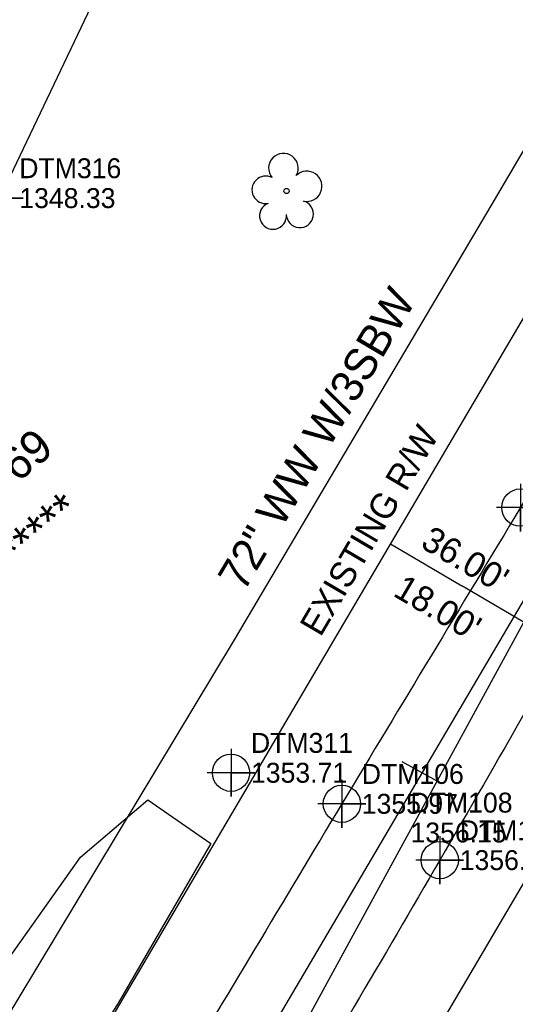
# Model space of a CAD drawing. Extents: x 1435573 to 1437263, y 981340 to 982884.
# Drawn here: x 1436076 to 1436138.2, y 982245.5 to 982369.2 of the extents above; entities that cross this region are included whole.
import ezdxf

# ---------------------------------------------------------------- set-up
doc = ezdxf.new("R2010")
doc.units = 0
for name, color, linetype in [('CTL Sheet Text', 7, 'Continuous'), ('Default Symbol CELL', 7, 'Continuous'), ('Default Symbol Cogo Elevation', 7, 'Continuous'), ('Default Symbol Cogo Number', 7, 'Continuous'), ('Exist DTM Crownline Cogo Elevation', 7, 'Continuous'), ('Exist DTM Crownline Cogo Number', 7, 'Continuous'), ('Exist Horizontal Alignment', 7, 'Continuous'), ('Exist Horizontal Baseline Alignment', 7, 'Continuous'), ('Exist Horizontal Baseline Alignment Tick small', 7, 'Continuous'), ('Exist Hydro Jurisdictional Stream or Body of Water', 7, 'Continuous'), ('Exist Hydro Stream or Body of Water Cogo Elevation', 7, 'Continuous'), ('Exist Hydro Stream or Body of Water Cogo Number', 7, 'Continuous'), ('Exist Hydro Stream or Body of Water Cogo Point CELL', 7, 'Continuous'), ('Exist Other Culture Fence Line', 7, 'Continuous'), ('Exist Other Culture Fence Line Text', 7, 'Continuous'), ('Exist Right of Way Line', 7, 'Continuous'), ('Exist Right of Way Line Text', 7, 'Continuous'), ('Exist Right of Way Width CELL', 7, 'Continuous'), ('Exist Roads EOP', 7, 'Continuous'), ('Exist Roads EOP Cogo Elevation', 7, 'Continuous'), ('Exist Roads EOP Cogo Number', 7, 'Continuous'), ('Exist Roads EOP Cogo Point CELL', 7, 'Continuous'), ('Exist Vegetation Tree CELL', 7, 'Continuous'), ('Exist Vegetation Woods Line', 7, 'Continuous')]:
    doc.layers.add(name, color=color, linetype=linetype)

msp = doc.modelspace()

# ---------------------------------------------------------------- linework, layer by layer
at = {"layer": 'Default Symbol CELL'}
msp.add_lwpolyline([(1436102.53, 982277.61), (1436102.53, 982271.61), (1436102.53, 982274.61), (1436105.53, 982274.61), (1436099.53, 982274.61)], dxfattribs=at)
msp.add_circle((1436102.53, 982274.61), 2.34, dxfattribs=at)
at = {"layer": 'Exist Horizontal Alignment'}
msp.add_line((1436018.3, 982090.66), (1436160.98, 982333.13), dxfattribs=at)
at = {"layer": 'Exist Horizontal Baseline Alignment'}
msp.add_line((1435840.71, 981747.05), (1436220.79, 982442.59), dxfattribs=at)
at = {"layer": 'Exist Horizontal Baseline Alignment Tick small'}
msp.add_line((1436128.43, 982273.57), (1436124.04, 982275.97), dxfattribs=at)
at = {"layer": 'Exist Hydro Jurisdictional Stream or Body of Water'}
msp.add_lwpolyline([(1435868.19, 982015.59), (1435900.37, 982051.1), (1435890.46, 982068.11), (1435899.75, 982073.74), (1435922.56, 982111.64), (1435976.46, 982187.79), (1435990.17, 982221.39), (1436012.44, 982254.73), (1436035.55, 982280.88), (1436050.71, 982320.86), (1436073.43, 982346.77), (1436085.85, 982372.72), (1436095.83, 982388.72), (1436115.7, 982405.3)], dxfattribs=at)
at = {"layer": 'Exist Hydro Stream or Body of Water Cogo Point CELL'}
msp.add_lwpolyline([(1436070.43, 982346.77), (1436076.43, 982346.77), (1436073.43, 982346.77), (1436073.43, 982343.77), (1436073.43, 982349.77)], dxfattribs=at)
at = {"layer": 'Exist Other Culture Fence Line'}
msp.add_lwpolyline([(1435979.98, 982088.94), (1436003.47, 982127.28), (1436023.88, 982160.05), (1436102.97, 982291.31), (1436135.2, 982345.79), (1436142.87, 982358.83), (1436158.39, 982359.45)], dxfattribs=at)
at = {"layer": 'Exist Right of Way Line'}
for p, q in [((1436002.79, 982099.79), (1436145.47, 982342.25)), ((1436033.82, 982081.53), (1436176.49, 982324))]:
    msp.add_line(p, q, dxfattribs=at)
at = {"layer": 'Exist Right of Way Width CELL'}
for p in [(1436122.57, 982303.34), (1436153.6, 982285.08)]:
    msp.add_line(p, (1436131.53, 982298.07), dxfattribs=at)
at = {"layer": 'Exist Roads EOP'}
for points in [[(1436168.25, 982354.25), (1436159.59, 982341.51), (1436138.87, 982307.91), (1436116.45, 982270.71), (1436094.59, 982234.3), (1436072.39, 982197.46), (1436049.68, 982158.52), (1436026.6, 982119.74), (1436003.23, 982078.86), (1435983.99, 982044.69), (1435963.78, 982007.01), (1435943.65, 981966.84), (1435922.15, 981922.09), (1435903.52, 981881.23), (1435884.45, 981840.59), (1435866.4, 981798.52)], [(1436177.12, 982349.86), (1436168.84, 982336.18), (1436150.23, 982301.68), (1436128.75, 982263.64), (1436107.21, 982226.88), (1436085.56, 982190.23), (1436062.44, 982151.3), (1436039.53, 982112.34), (1436015.81, 982071.47), (1435996.75, 982037.94), (1435976.48, 982000.31), (1435956.5, 981960.4), (1435935.19, 981915.99), (1435916.41, 981875.42), (1435898.23, 981835.84), (1435879.29, 981793.08)]]:
    msp.add_spline(points, degree=3, dxfattribs=at)
at = {"layer": 'Exist Roads EOP Cogo Point CELL'}
for points in [[(1436138.87, 982310.91), (1436138.87, 982304.91), (1436138.87, 982307.91), (1436141.87, 982307.91), (1436135.87, 982307.91)], [(1436116.45, 982273.71), (1436116.45, 982267.71), (1436116.45, 982270.71), (1436119.45, 982270.71), (1436113.45, 982270.71)], [(1436128.75, 982266.64), (1436128.75, 982260.64), (1436128.75, 982263.64), (1436131.75, 982263.64), (1436125.75, 982263.64)]]:
    msp.add_lwpolyline(points, dxfattribs=at)
for centre in [(1436138.87, 982307.91), (1436116.45, 982270.71), (1436128.75, 982263.64)]:
    msp.add_circle(centre, 2.34, dxfattribs=at)
at = {"layer": 'Exist Vegetation Tree CELL'}
msp.add_line((1436109.5, 982347.66), (1436109.5, 982347.66), dxfattribs=at)
msp.add_circle((1436109.5, 982347.66), 0.326, dxfattribs=at)
for centre, radius, start, end in [((1436109.11, 982350.53), 1.86, 330.1651, 219.7134), ((1436112.05, 982348.25), 1.9, 257.1011, 134.1999), ((1436106.89, 982347.81), 1.73, 62.6636, 279.3457), ((1436111.17, 982344.76), 1.7, 181.2822, 74.56), ((1436107.8, 982344.54), 1.69, 111.5671, 6.231)]:
    msp.add_arc(centre, radius, start, end, dxfattribs=at)
at = {"layer": 'Exist Vegetation Woods Line'}
msp.add_lwpolyline([(1436022.3, 982179.95), (1436034.94, 982194.02), (1436044.86, 982209.69), (1436061.4, 982232.18), (1436074.09, 982250.54), (1436083.63, 982264.01), (1436092.08, 982271.21), (1436099.98, 982265.71), (1436088.34, 982245.67), (1436068.18, 982213.85), (1436049.75, 982183.61), (1436035.71, 982164.59), (1436028.24, 982156.34), (1436019.56, 982156.9), (1436018.12, 982165.84), (1436022.3, 982179.95)], dxfattribs=at)

# ---------------------------------------------------------------- texts
at = {"layer": 'CTL Sheet Text'}
for s, p in [('DISK IN HEADWALL 145 HLZ 1969', (1436011.71, 982258.13)), ('****************************************', (1436017.02, 982251.7))]:
    msp.add_text(s, height=4.1667, rotation=39.5399, dxfattribs=at).set_placement(p)
at = {"layer": 'Default Symbol Cogo Elevation'}
msp.add_text('1353.71', height=2.5, dxfattribs=at).set_placement((1436105.03, 982273.36))
at = {"layer": 'Default Symbol Cogo Number'}
msp.add_text('DTM311', height=2.5, dxfattribs=at).set_placement((1436105.03, 982277.11))
at = {"layer": 'Exist DTM Crownline Cogo Elevation'}
msp.add_text('1356.15', height=2.5, dxfattribs=at).set_placement((1436125.07, 982265.86))
at = {"layer": 'Exist DTM Crownline Cogo Number'}
msp.add_text('DTM108', height=2.5, dxfattribs=at).set_placement((1436125.07, 982269.61))
at = {"layer": 'Exist Hydro Stream or Body of Water Cogo Elevation'}
msp.add_text('1348.33', height=2.5, dxfattribs=at).set_placement((1436075.93, 982345.52))
at = {"layer": 'Exist Hydro Stream or Body of Water Cogo Number'}
msp.add_text('DTM316', height=2.5, dxfattribs=at).set_placement((1436075.93, 982349.27))
at = {"layer": 'Exist Other Culture Fence Line Text'}
msp.add_text('72" WW W/3SBW', height=4, rotation=59.3896, dxfattribs=at).set_placement((1436104.14, 982297.21))
at = {"layer": 'Exist Right of Way Line Text'}
msp.add_text('EXISTING R/W', height=3.2, rotation=59.5252, dxfattribs=at).set_placement((1436113.77, 982291.55))
at = {"layer": 'Exist Right of Way Width CELL'}
for s, p in [("36.00'", (1436126.18, 982302.99)), ("18.00'", (1436122.74, 982296.9))]:
    msp.add_text(s, height=3.2, rotation=329.5252, dxfattribs=at).set_placement(p)
at = {"layer": 'Exist Roads EOP Cogo Elevation'}
for s, p in [('1355.97', (1436118.95, 982269.46)), ('1356.01', (1436131.25, 982262.39))]:
    msp.add_text(s, height=2.5, dxfattribs=at).set_placement(p)
at = {"layer": 'Exist Roads EOP Cogo Number'}
for s, p in [('DTM106', (1436118.95, 982273.21)), ('DTM110', (1436131.25, 982266.14))]:
    msp.add_text(s, height=2.5, dxfattribs=at).set_placement(p)

doc.saveas('drawing.dxf')
